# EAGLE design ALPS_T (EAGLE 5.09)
MFG: AVX; PN: TCJR106M006R0500
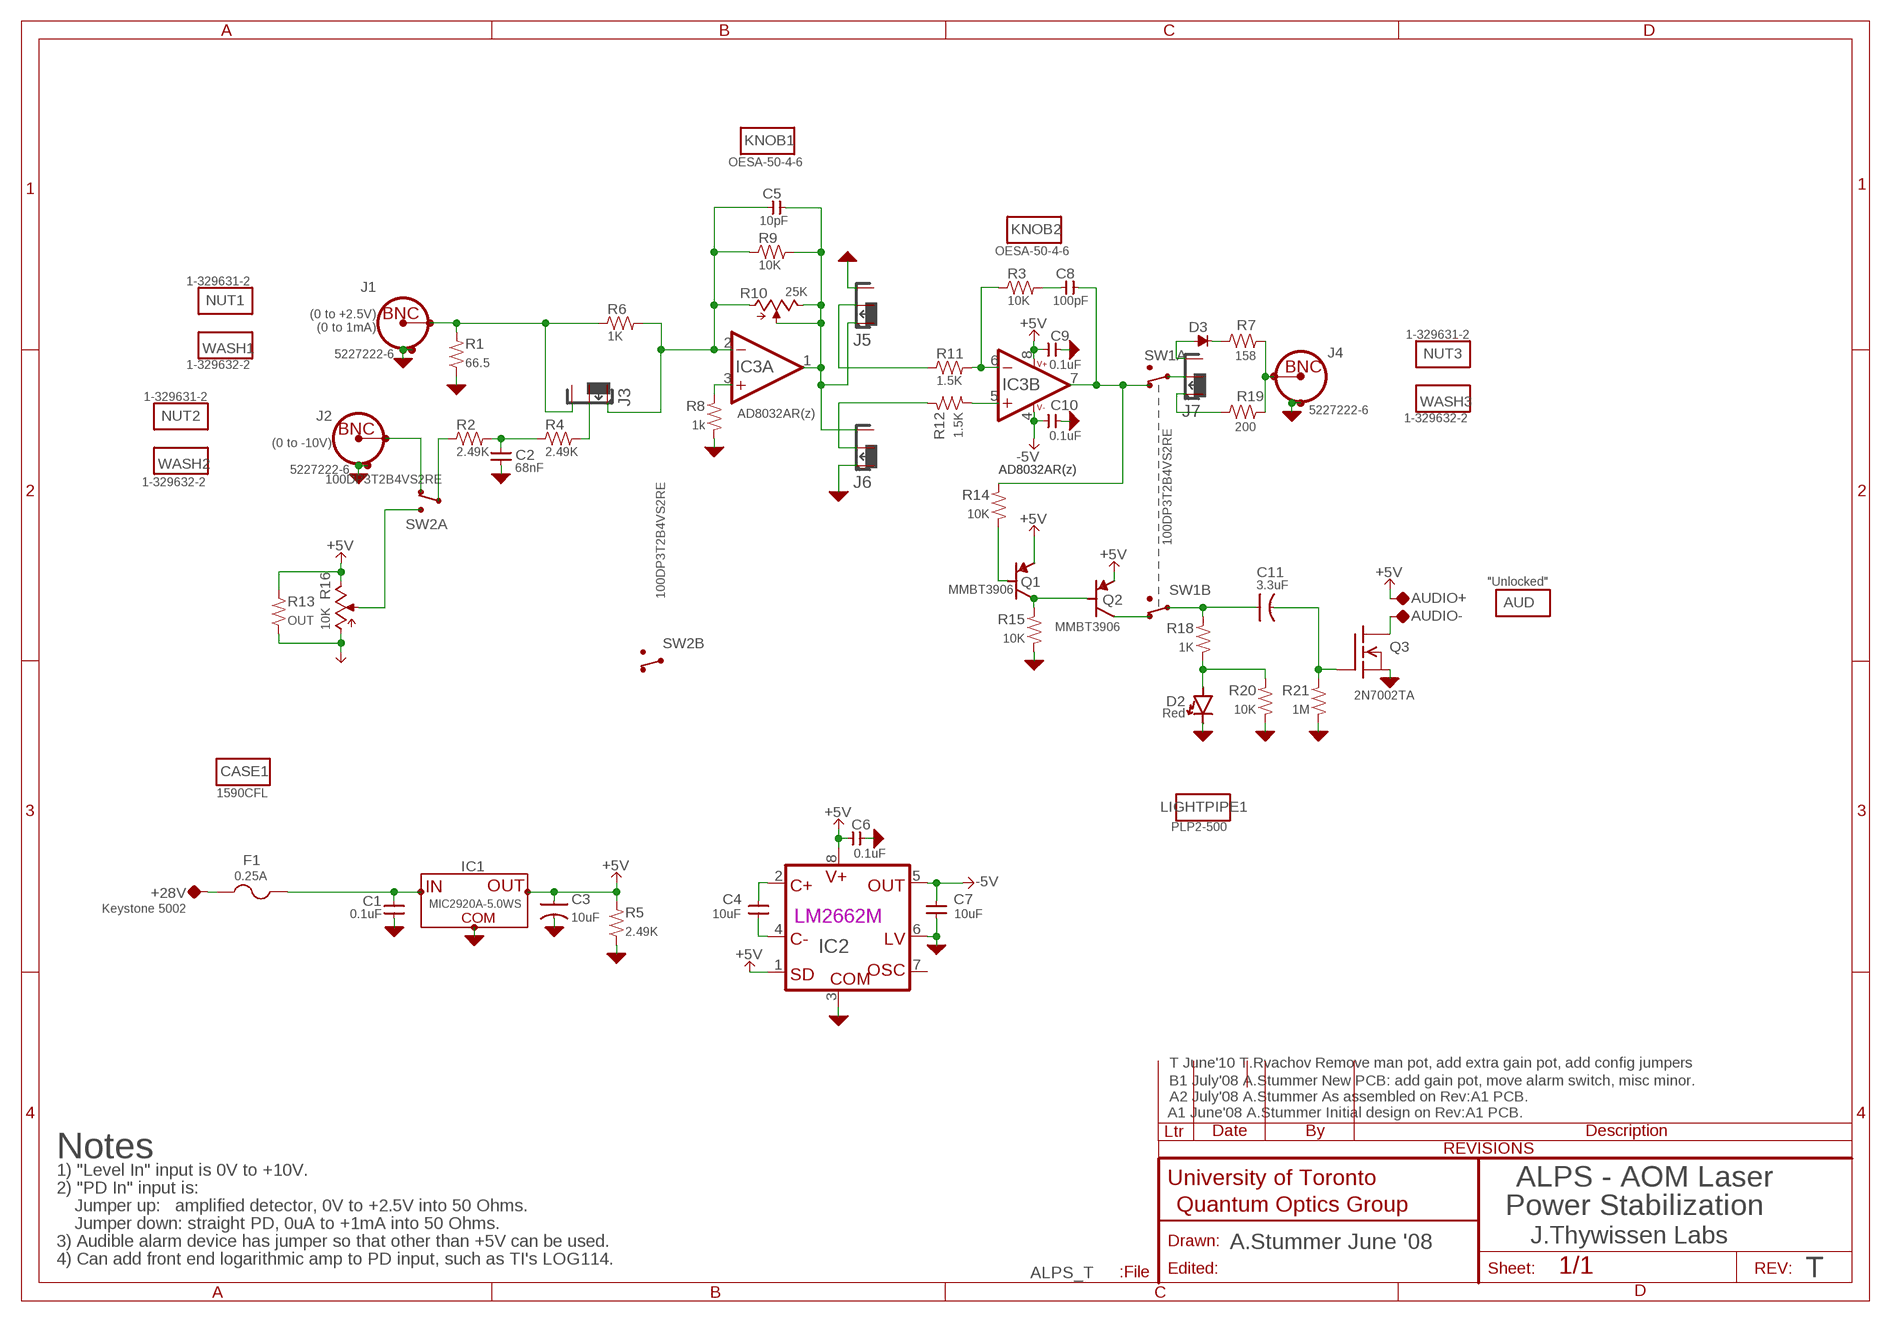
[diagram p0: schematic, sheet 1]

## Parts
+28V  Keystone 5002  TP-0.042B  [TP-0.042B]
AUD  "Unlocked"  MISC  [MISC]
AUDIO+  Keystone 5002  TP-0.042B  [TP-0.042B]
AUDIO-  Keystone 5002  TP-0.042B  [TP-0.042B]
C1  0.1uF  CAP-V-0805  [2012(0805)]
C2  68nF  CAP-V-0805  [2012(0805)]
C3  10uF  CAP-POL-1206  [3216(1206)]
C4  10uF  CAP-V-0805  [2012(0805)]
C5  10pF  CAP-H-0805  [2012(0805)]
C6  0.1uF  CAP-H-0805  [2012(0805)]
C7  10uF  CAP-V-0805  [2012(0805)]
C8  100pF  CAP-H-0805  [2012(0805)]
C9  0.1uF  CAP-H-0805  [2012(0805)]
C10  0.1uF  CAP-H-0805  [2012(0805)]
C11  3.3uF  CAP-POL-0805  [2012(0805)]
CASE1  1590CFL  MISC  [MISC]
D2  Red  LED-1209  [1209]
D3  DIODE,GENERIC-SOD123  [SOD123]
F1  0.25A  FUSE-5X20-4  [FUSE]
IC1  MIC2920A-5.0WS  78-SOT223  [SOT223]
IC2  LM2662M  LM2663M  [SOIC-8]
IC3  AD8032AR(z)  OPAMP_DUAL-SOIC8  [SOIC-8]
J1  5227222-6  CONN-BNC-TYPE1VERT  [CONN-BNC-AMP-TYPE1VERT]
J2  5227222-6  CONN-BNC-TYPE1VERT  [CONN-BNC-AMP-TYPE1VERT]
J3  JUMPER-1X3-3  [JUMPER-3]
J4  5227222-6  CONN-BNC-TYPE1VERT  [CONN-BNC-AMP-TYPE1VERT]
J5  JUMPER-1X3-3  [JUMPER-3]
J6  JUMPER-1X3-3  [JUMPER-3]
J7  JUMPER-1X3-3  [JUMPER-3]
KNOB1  OESA-50-4-6  MISC  [MISC]
KNOB2  OESA-50-4-6  MISC  [MISC]
LIGHTPIPE1  PLP2-500  MISC  [MISC]
NUT1  1-329631-2  MISC  [MISC]
NUT2  1-329631-2  MISC  [MISC]
NUT3  1-329631-2  MISC  [MISC]
Q1  MMBT3906  BJT-PNP-SOT23  [SOT23@1]
Q2  MMBT3906  BJT-PNP-SOT23  [SOT23@1]
Q3  2N7002TA  MOSFET-N-SOT23  [SOT23@1]
R1  66.5  R-V-0805  [2012(0805)]
R2  2.49K  R-H-0805  [2012(0805)]
R3  10K  R-H-0805  [2012(0805)]
R4  2.49K  R-H-0805  [2012(0805)]
R5  2.49K  R-V-0805  [2012(0805)]
R6  1K  R-H-0805  [2012(0805)]
R7  158  R-H-0805  [2012(0805)]
R8  1k  R-V-0805  [2012(0805)]
R9  10K  R-H-0805  [2012(0805)]
R10  25K  POT-PRECISION_SPR_RV8  [PRECISION-SPR-RV8(POT)]
R11  1.5K  R-H-0805  [2012(0805)]
R12  1.5K  R-V-0805  [2012(0805)]
R13  OUT  R-V-0805  [2012(0805)]
R14  10K  R-V-0805  [2012(0805)]
R15  10K  R-V-0805  [2012(0805)]
R16  10K  POT-PRECISION_SPR_RV8  [PRECISION-SPR-RV8(POT)]
R18  1K  R-V-0805  [2012(0805)]
R19  200  R-H-0805  [2012(0805)]
R20  10K  R-V-0805  [2012(0805)]
R21  1M  R-V-0805  [2012(0805)]
SW1  100DP3T2B4VS2RE  SWITCH_DPDT-ESWITCH_100DP?VS2  [SWITCH-ESWITCH_100DP?VS2]
SW2  100DP3T2B4VS2RE  SWITCH_DPDT-ESWITCH_100DP?VS2  [SWITCH-ESWITCH_100DP?VS2]
WASH1  1-329632-2  MISC  [MISC]
WASH2  1-329632-2  MISC  [MISC]
WASH3  1-329632-2  MISC  [MISC]

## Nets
+5V: AUDIO+.TP C3.2(POS) C6.1 C9.1 IC1.3(OUT) IC2.1(SD) IC2.8(V+) IC3.8(.:V+) Q1.2(E) Q2.2(E) R5.2 R13.2 R16.CW
-5V: C7.2 C10.1 IC2.5(OUT) IC3.4(.:V-)
AGND: C1.1 C2.1 C3.1(NEG) C6.2 C7.1 C9.2 C10.2 D2.K(C) IC1.2@1(COM) IC2.3(COM) IC2.6(LV) J1.SHIELD1 J1.SHIELD2 J2.SHIELD1 J2.SHIELD2 J4.SHIELD1 J4.SHIELD2 J5.3 J6.1 Q3.2(S) R1.1 R5.1 R8.1 R15.1 R20.1 R21.1
N$1: J7.2 SW1.C1(A:COM1)
N$2: C8.2 IC3.7(B:OUT) R14.2 SW1.NC1(A:NC1)
N$3: IC3.6(B:-IN) R3.1 R11.2
N$4: IC3.5(B:+IN) R12.1
N$5: J7.1 R19.1
N$6: C8.1 R3.2
N$7: R2.1 SW2.C1(A:COM1)
N$8: J2.CONDUCTOR SW2.NC1(A:NC1)
N$9: Q1.3(C) Q2.1(B) R15.2
N$10: R13.1 R16.CCW
N$11: Q1.1(B) R14.1
N$12: C11.2(POS) R18.2 SW1.C2(B:COM1)
N$13: D2.A R18.1 R20.2
N$14: Q2.3(C) SW1.NC2(B:NC1)
N$15: C11.1(NEG) Q3.1(G) R21.2
N$16: AUDIO-.TP Q3.3(D)
N$18: C4.2 IC2.2(C+)
N$19: +28V.TP F1.1A
N$20: C1.2 F1.2A IC1.1(VI)
N$21: C5.2 IC3.1(A:OUT) J5.1 J6.3 R9.2 R10.CW R10.W
N$22: C5.1 IC3.2(A:-IN) J3.1 R6.2 R9.1 R10.CCW
N$23: J3.2 R4.2
N$24: J6.2 R12.2
N$25: IC3.3(A:+IN) R8.2
N$26: C4.1 IC2.4(C-)
N$27: C2.2 R2.2 R4.1
N$28: J5.2 R11.1
N$29: J1.CONDUCTOR J3.3 R1.2 R6.1
N$30: J4.CONDUCTOR R7.2 R19.2
N$31: D3.A J7.3
N$32: R16.W SW2.NO1(A:NO1)
N$33: D3.C R7.1
Unconnected: IC2.7(OSC) SW1.NO1(A:NO1) SW1.NO2(B:NO1) SW2.C2(B:COM1) SW2.NC2(B:NC1) SW2.NO2(B:NO1)

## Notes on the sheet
- (0 to +2.5V)
- (0 to 1mA)
- (0 to -10V)
- T June'10 T.Rvachov Remove man pot, add extra gain pot, add config jumpers
- B1 July'08 A.Stummer New PCB: add gain pot, move alarm switch, misc minor.
- A2 July'08 A.Stummer As assembled on Rev:A1 PCB.
- A1 June'08 A.Stummer Initial design on Rev:A1 PCB.
- Notes
- 1) "Level In" input is 0V to +10V.
- ALPS - AOM Laser
- 2) "PD In" input is:
- Jumper up:   amplified detector, 0V to +2.5V into 50 Ohms. | Power Stabilization
- Jumper down: straight PD, 0uA to +1mA into 50 Ohms.
- 3) Audible alarm device has jumper so that other than +5V can be used. | A.Stummer June '08 | J.Thywissen Labs
- 4) Can add front end logarithmic amp to PD input, such as TI's LOG114.
- T

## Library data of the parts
+28V AUDIO+ AUDIO- = QuantumOptics:TP: Testpoint, test point on schematic, on PCB either SMT pad, small hole or loop style TP.
AUD CASE1 KNOB1 KNOB2 LIGHTPIPE1 NUT1-NUT3 WASH1-WASH3 = QuantumOptics:MISC: Miscellaneous Part, just a placeholder for miscellaeous parts
C1 C2 C4 C7 = QuantumOptics:CAP-V-: Cap, SMT and Through-hole, 0402 and up.
C3 C11 = QuantumOptics:CAP-POL-: Capacitor, Polarized, SMT 0805 and up, probably tantalum.
C5 C6 C8-C10 = QuantumOptics:CAP-H-: Cap, SMT and Through-hole, 0402 and up.
D2 = QuantumOptics:LED: LED
D3 = QuantumOptics:DIODE,GENERIC: Diode, Generic, plain old vanilla diodes.
F1 = QuantumOptics:FUSE: Fuse
IC1 = QuantumOptics:78*: Positive regulator, probably fixed output. E.g. SOT-223 Micrel MIC2920, http://www.micrel.com/_PDF/mic2920.pdf e.g. uA78L05ACPK, http://www-s.ti.com/sc/ds/ua78l05a.pdf
IC2 = QuantumOptics:LM2663: LM2663, switched cap DC-DC converter. Inverter, doubler, supply splitter.
IC3 = QuantumOptics:OPAMP_DUAL: Dual Op Amp, common pinouts. Based on http://www.analog.com/static/imported-files/data_sheets/AD8651_8652.pdf
J1 J2 J4 = QuantumOptics:CONN-BNC: BNC PCB, horizontal or vertical, e.g. vertical: Amp 227677-1, nut 1-329631-2, shoulder washer 330620. The two shield connections allow the assembly on either side of the board. Horiz isolated: 5227222-6, http://catalog.tycoelectronics.com/TE/bin/TE.Connect?C=1&M=BYPN&TCPN=5227222-6&RQPN=5227222-6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; DESC: Input?
J3 J5-J7 = QuantumOptics:JUMPER-1X3: Jumper, header, SIP on 0.1" grid, for option selection.
Q1 Q2 = QuantumOptics:BJT-PNP: PNP BJT, generic, p/n defined by VALUE field. E.g. Fairchild MMBT3906 (abs max 40V, 200mA. hFE>80@10mA.
Q3 = QuantumOptics:MOSFET-N: Mosfet, N-Channel, generic enhancement mode N-FET.
R1 R5 R8 R12-R15 R18 R20 R21 = QuantumOptics:R-V-*: Resistor, SMT & Through-Hole, vertical symbol
R2-R4 R6 R7 R9 R11 R19 = QuantumOptics:R-H-*: Resistor, SMT & Through-Hole, horizontal symbol
R10 R16 = QuantumOptics:POT: Pot, regular or trimpot
SW1 SW2 = QuantumOptics:SWITCH_DPDT: Switch, DPDT

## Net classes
0 default: width 0.178 mm, drill 0.508 mm, clearance 0.178 mm

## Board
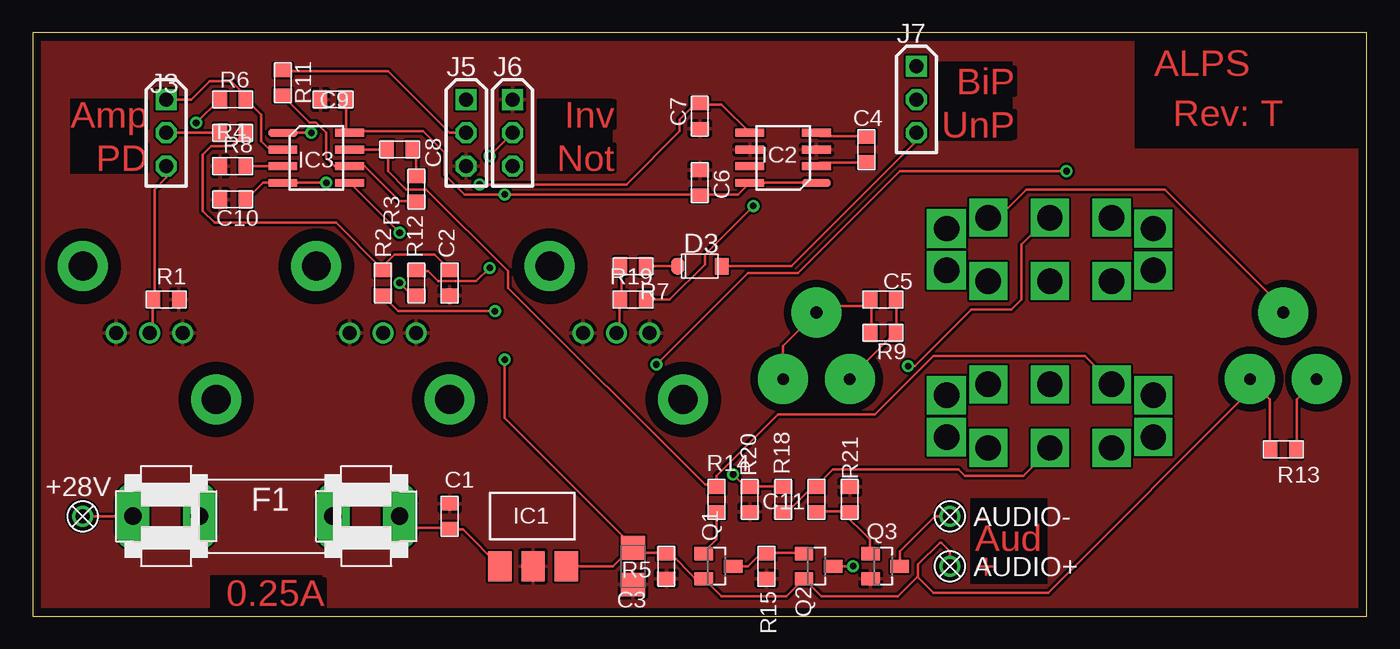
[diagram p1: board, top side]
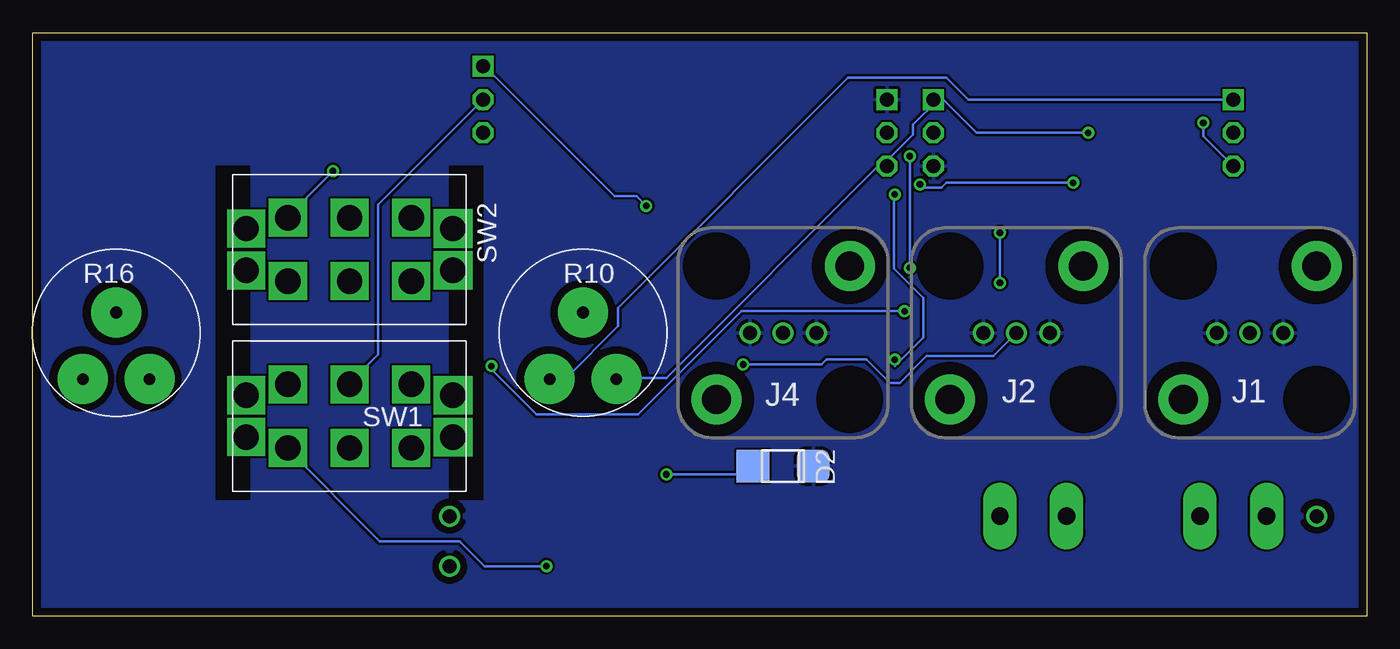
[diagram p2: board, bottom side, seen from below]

Size 101.6 x 44.45 mm. Coordinates in mm from the lower left corner, seen from the top.
Outline: 0,0 101.6,0 101.6,44.45 0,44.45 0,0
Copper layers (1+16): Top 0.035mm / dielectric 1.5mm / Bottom 0.035mm
Design rules "DRC standard check": minimum track width 7mil, minimum drill 20mil, track to track 7mil, track to pad 7mil, pad to pad 7mil, via to via 7mil, smd to smd 0mil, copper to edge 25mil, drill to drill 8mil, minimum pad ring 10mil, minimum via ring 8mil, stop-mask expansion 4mil, vias tented up to drill 0mil, thermal gap 10mil
tRestrict: area 54.7,15.6 to 59.6,20.5; area 59.8,15.6 to 64.7,20.5; area 90.3,15.6 to 95.2,20.5; area 95.4,15.6 to 100.4,20.5; area 57.2,20.7 to 62.2,25.6; area 92.8,20.7 to 97.8,25.6; 19 lines
bRestrict: area 54.7,15.6 to 59.6,20.5; area 59.8,15.6 to 64.7,20.5; area 90.3,15.6 to 95.2,20.5; area 95.4,15.6 to 100.4,20.5; area 57.2,20.7 to 62.2,25.6; area 92.8,20.7 to 97.8,25.6

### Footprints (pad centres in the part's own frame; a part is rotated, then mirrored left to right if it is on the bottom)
TP-0.042B = drill 1.067 round: TP 0,0
2012(0805) = smd 1.016 x 1.397: 1 -0.953,0; 2 0.953,0
3216(1206) = smd 1.8 x 1.8: 1 -1.4,0; 2 1.4,0
1209 = smd 2.5 x 2.5: A 2.3,0; K -2.3,0
SOD123 = smd 1.016 x 1.27: A 1.676,0; C -1.676,0
FUSE = drill 1.321 pad 2.54 long: 1A -10.16,0; 1B -5.08,0; 2A 10.16,0; 2B 5.08,0
SOT223 = smd 1.778 x 2.286: 1 -2.54,-2.54; 2@1 0,-2.54; 3 2.54,-2.54
SOIC-8 = smd 0.6 x 2.2: 1 -1.27,-2.54; 2 0,-2.54; 3 1.27,-2.54; 4 2.54,-2.54; 5 2.54,2.54; 6 1.27,2.54; 7 0,2.54; 8 -1.27,2.54
CONN-BNC-AMP-TYPE1VERT = drill 1.067 round: CONDUCTOR 0,0; SHIELD1 -2.54,0; SHIELD2 2.54,0 | drill 2.184 pad 3.81 round: MTG1 -5.08,-5.08; MTG2 5.08,5.08
JUMPER-3 = drill 1.067 square: 1 0,2.54 | drill 1.067 octagon: 2 0,0; 3 0,-2.54
SOT23@1 = smd 1 x 1.4: 1 -0.953,-0.953; 2 0.953,-0.953; 3 0,1.27
PRECISION-SPR-RV8(POT) = drill 0.889 pad 3.81 round: CCW -2.54,-3.531; CW 2.54,-3.531; W 0,1.549
SWITCH-ESWITCH_100DP?VS2 = drill 1.93 square: C1 -2.42,0; C2 2.42,0; MTG3 1.595,-7.875; MTG4 -1.595,-7.875; NC1 -2.42,-4.7; NC2 2.42,-4.7; NO1 -2.42,4.7; NO2 2.42,4.7 | drill 1.93 pad 2.946 square: MTG1 -1.595,7.875; MTG2 1.595,7.875

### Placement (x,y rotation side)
+28V  3.81,7.62 180 top
AUD  not placed on the board
AUDIO+  69.85,3.81 270 top
AUDIO-  69.85,7.62 0 top
C1  31.75,7.62 270 top
C2  31.75,25.4 90 top
C3  45.72,3.81 90 top
C4  63.5,35.56 270 top
C5  64.77,24.13 180 top
C6  50.8,33.02 90 top
C7  50.8,38.1 90 top
C8  27.94,35.56 180 top
C9  22.86,39.37 180 top
C10  15.24,31.75 180 top
C11  59.69,8.89 90 top
CASE1  not placed on the board
D2  44.45,11.43 180 bottom
D3  50.8,26.67 0 top
F1  17.78,7.62 0 top
IC1  38.1,6.35 0 top
IC2  57.15,34.29 90 top
IC3  21.59,35.56 270 top
J1  8.89,21.59 0 bottom
J2  26.67,21.59 0 bottom
J3  10.16,36.83 0 top
J4  44.45,21.59 0 bottom
J5  33.02,36.83 0 top
J6  36.56,36.83 0 top
J7  67.31,39.37 0 top
KNOB1  not placed on the board
KNOB2  not placed on the board
LIGHTPIPE1  not placed on the board
NUT1  not placed on the board
NUT2  not placed on the board
NUT3  not placed on the board
Q1  52.07,3.81 270 top
Q2  59.69,3.81 270 top
Q3  64.77,3.81 270 top
R1  10.16,24.13 180 top
R2  26.67,25.4 90 top
R3  29.21,32.55 90 top
R4  15.24,36.83 180 top
R5  48.26,3.81 90 top
R6  15.24,39.37 0 top
R7  45.72,26.67 180 top
R8  15.24,34.29 0 top
R9  64.77,21.59 180 top
R10  59.69,21.59 0 bottom
R11  19.05,40.64 270 top
R12  29.21,25.4 90 top
R13  95.25,12.7 180 top
R14  52.07,8.89 90 top
R15  55.88,3.81 90 top
R16  95.25,21.59 0 bottom
R18  57.15,8.89 270 top
R19  45.72,24.13 180 top
R20  54.61,8.89 90 top
R21  62.23,8.89 270 top
SW1  77.47,15.24 270 bottom
SW2  77.47,27.94 270 bottom
U$18  [TITLEBLOCK_PCB]  not placed on the board
WASH1  not placed on the board
WASH2  not placed on the board
WASH3  not placed on the board

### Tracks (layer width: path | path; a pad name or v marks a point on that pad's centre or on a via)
+5V  (via drill 0.51)
  Top 0.203: C9.1 23.88,39.37 23.88,37.08 IC3.8 24.13,36.96 29.72,36.96 31.37,35.31 31.37,33.66 32.89,32.13 v35.94,32.13 50.8,32.13 | 50.8,32.13 53.72,32.13 IC2.8 IC2.1 | 50.8,32.13 C6.1 | R13.2 94.23,12.7 94.23,16.51 92.71,18.03 R16.CW 93.09,17.53 77.34,1.78 68.58,1.78 67.37,2.98 | IC1.3 44.2,3.81 45.72,5.33 | AUDIO+.TP 69.85,4.95 69.22,5.59 69.09,5.59 67.44,3.94 67.44,3.05 67.37,2.98 | 67.37,2.98 65.91,1.52 60.07,1.52 Q2.2 57.4,1.52 52.45,1.52 Q1.2 51.05,2.92 50.42,2.92 48.64,4.7 48.26,4.7 R5.2 48.26,4.83 46.1,4.83 C3.2 45.72,5.33 | v35.94,19.54 35.94,15.11 45.72,5.33
  Bottom 0.18: v35.94,19.54 35.94,19.06 33.75,21.25 33.75,24.25 36,26.5 36,32.07 v35.94,32.13
-5V  (via drill 0.51)
  Top 0.203: C10.1 16.26,31.75 17.53,33.02 IC3.4 v22.35,33.02 | 50.8,38.99 52.45,38.99 IC2.5 | v34.04,32.89 45.21,32.89 49.28,36.96 49.28,37.85 50.42,38.99 50.8,38.99 | 50.8,38.99 C7.2
  Bottom 0.203: v22.35,33.02 32,33.02 32.38,32.64 33.78,32.64 v34.04,32.89
AGND
  pour Top: 0,0 101.6,0 101.6,35.56 83.83,35.56 83.83,44.45 0,44.45
  pour Bottom: 0,0 101.6,0 101.6,44.45 0,44.45
N$1
  Bottom 0.203: J7.2 75.31,31.37 75.31,19.94 77.47,17.78 SW1.C1
N$2
  Top 0.203: IC3.7 C8.2 27.05,35.56 27.05,33.91 28.45,32.51 29.97,32.51 36.2,26.29 36.2,25.02 51.18,10.03 52.07,10.03 | 52.07,10.03 52.07,10.67 56.77,15.37 64.14,15.37 68.58,19.81 80.14,19.81 82.17,17.78 SW1.NC1 | 52.07,10.03 R14.2 52.07,9.91
N$3
  Top 0.203: R11.2 19.05,39.62 21.08,37.59 21.59,37.59 22.35,36.83 22.35,34.92 22.99,34.29 IC3.6 25.27,34.29 27.94,31.62 29.21,31.62 R3.1
N$4  (via drill 0.51)
  Top 0.203: v27.94,25.4 28.83,24.51 29.21,24.51 R12.1 | v27.94,29.21 IC3.5
  Bottom 0.203: v27.94,25.4 v27.94,29.21
N$5  (via drill 0.51)
  Top 0.203: v54.88,31.25 51.18,27.56 51.18,26.8 48.51,24.13 R19.1
  Bottom 0.18: 57.28,32 55.63,32 v54.88,31.25
  Bottom 0.203: 57.28,32 67.18,41.91 J7.1
N$6
  Top 0.203: R3.2 29.21,35.31 28.96,35.56 C8.1
N$7  (via drill 0.51)
  Top 0.203: v35.2,23.24 27.81,23.24 26.67,24.38 R2.1 | v66.67,19.05 67.18,19.05 71.5,23.37 74.55,23.37 75.31,24.13 75.31,28.32 77.47,30.48 SW2.C1
  Bottom 0.203: v35.2,23.24 47.62,23.24 55.5,15.37 63.25,15.37 66.67,18.8 v66.67,19.05
N$8  (via drill 0.51)
  Top 0.203: v47.5,19.18 54.48,26.16 58.29,26.16 66.04,33.91 v78.74,33.91
  Bottom 0.203: J2.CONDUCTOR 28.45,19.81 33.53,19.81 35.56,17.78 36.32,17.78 38.1,19.56 41.15,19.56 41.53,19.18 v47.5,19.18 | v78.74,33.91 82.17,30.48 SW2.NC1
N$9
  Top 0.203: Q2.1 58.67,4.83 55.88,4.83 R15.2 55.88,4.7 55.37,4.7 54.48,3.81 Q1.3
N$10
  Top 0.203: R13.1 96.27,12.7 96.27,16.51 97.79,18.03 R16.CCW
N$11
  Top 0.203: R14.1 52.07,5.84 51.05,4.83 Q1.1
N$12
  Top 0.203: R18.2 57.15,8 57.53,8 59.31,9.78 59.69,9.78 C11.2 59.69,9.91 60.96,11.18 70.48,11.18 70.99,10.67 75.44,10.67 77.47,12.7 SW1.C2
N$13  (via drill 0.51)
  Top 0.203: 54.61,9.91 57.15,9.91 R18.1 | 54.61,9.91 54.23,9.91 v53.34,10.79 | 54.61,9.91 R20.2
  Bottom 0.203: v53.34,10.79 47.5,10.79 46.86,11.43 D2.A
N$14  (via drill 0.51)
  Top 0.203: Q2.3 v62.48,3.81
  Bottom 0.203: v62.48,3.81 67.18,3.81 69.09,5.71 75.18,5.71 82.17,12.7 SW1.NC2
N$15
  Top 0.203: 61.59,8 62.23,8 R21.2 61.59,8 | 61.59,8 59.69,8 C11.1 | 61.59,8 63.75,5.84 63.75,4.83 Q3.1
N$16
  Top 0.203: Q3.3 66.04,4.95 68.71,7.62 AUDIO-.TP
N$18
  Top 0.203: IC2.2 59.94,34.54 63.5,34.54 C4.2
N$19
  Top 0.203: +28V.TP F1.1A
N$20
  Top 0.203: F1.2A 28.83,6.73 31.75,6.73 C1.2 31.75,6.6 32.77,6.6 IC1.1
N$21  (via drill 0.51)
  Top 0.203: 63.88,23.62 63.88,24.13 C5.2 63.88,23.62 | 63.88,23.62 63.88,21.59 R9.2 | 63.88,23.62 60.07,23.62 59.69,23.24 R10.W 59.69,23.11 57.15,20.57 R10.CW | IC3.1 v21.21,36.83
  Bottom 0.203: v21.21,36.83 29.72,36.83 32.26,39.37 32.64,39.37 | 32.64,39.37 34.54,37.47 34.54,36.7 36.45,34.8 36.45,34.29 J6.3 37.21,34.29 53.34,18.16 57.15,18.16 R10.CW | 32.64,39.37 J5.1
N$22
  Top 0.203: IC3.2 18.03,35.56 17.4,36.2 17.4,38.23 16.26,39.37 R6.2 16.13,39.37 16.13,39.75 15.11,40.77 13.46,40.77 12.06,39.37 J3.1 | C5.1 65.79,24.13 65.79,21.59 R9.1 65.66,21.59 62.23,18.16 R10.CCW
  Bottom 0.203: J3.1 30.35,39.37 32,41.02 39.5,41.02 57.02,23.5 57.02,22.1 60.96,18.16 62.23,18.16 R10.CCW
N$23
  Top 0.203: J3.2 R4.2
N$24  (via drill 0.51)
  Top 0.203: v34.8,26.54 33.78,25.53 30.86,25.53 30.1,26.29 29.21,26.29 R12.2 | v34.8,35.05 36.58,36.83 J6.2
  Bottom 0.203: v34.8,26.54 v34.8,35.05
N$25
  Top 0.203: R8.2 IC3.3
N$26
  Top 0.203: IC2.4 59.94,36.58 63.5,36.58 C4.1
N$27
  Top 0.203: 26.54,26.54 26.67,26.42 R2.2 26.54,26.54 | 26.54,26.54 23.11,29.97 13.84,29.97 12.95,30.86 12.95,35.18 13.59,35.81 15.11,35.81 16.13,36.83 R4.1 | 26.54,26.54 27.56,27.56 30.61,27.56 31.75,26.42 C2.2
N$28
  Top 0.203: J5.2 31.75,36.83 27.05,41.53 19.05,41.53 R11.1
N$29  (via drill 0.51)
  Top 0.203: J1.CONDUCTOR 9.14,21.84 9.14,24.13 R1.2 9.27,24.13 9.27,32.51 10.16,33.4 J3.3 | v12.45,37.59 14.22,39.37 R6.1
  Bottom 0.203: v12.45,37.59 12.45,36.58 J3.3
N$30
  Top 0.203: R7.2 44.83,26.67 44.83,24.13 R19.2 44.7,24.13 44.7,21.84 J4.CONDUCTOR
N$31
  Top 0.203: J7.3 67.31,36.2 57.78,26.67 D3.A
N$32
  Top 0.203: SW2.NO1 72.77,30.48 73.66,30.48 75.69,32.51 86.23,32.51 95.25,23.5 R16.W
N$33
  Top 0.203: R7.1 D3.C

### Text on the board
Top: ALPS | BiP | Amp | Inv | Rev: T | UnP | PD | Not | - | Aud | 0.25A | +
Document: A. Stummer July'08 | T | 0.2mm(0.008") | 0.2mm(0.008") | 0.2mm(0.008") | 0.125mm(0.005") | 0.125mm(0.005") | Following are misc parts: | B1 July'08 A.Stummer Redesign. | A2 July'08 A.Stummer As assembled on Rev:A1 PCB. | A1 June'08 A.Stummer Initial design on Rev:A1 PCB.
Text: ALPS - AOM Laser | Power Stabilization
